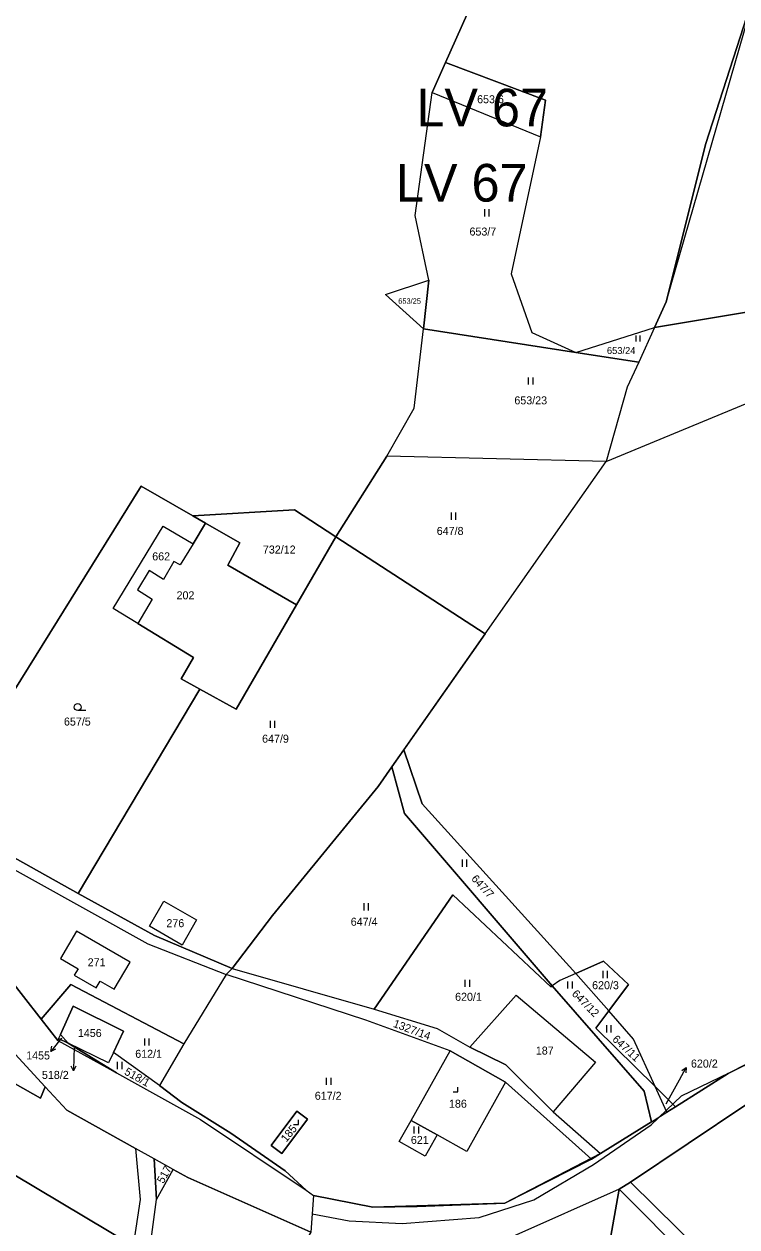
# Model space of a CAD drawing. Extents: x -588699 to -585793, y -1060280 to -1056731.
# Drawn here: x -586434.8 to -586283.2, y -1058797.6 to -1058542.2 of the extents above; entities that cross this region are included whole.
import ezdxf

# ---------------------------------------------------------------- set-up
doc = ezdxf.new("R2010")
doc.units = 0
for name, color, linetype in [('Druh pozemku', 7, 'Continuous'), ('Lesy', 7, 'Continuous'), ('Parcela nároku', 7, 'Continuous'), ('Parcelní číslo', 7, 'Continuous'), ('Silnice', 7, 'Continuous'), ('Vnější obvod_převzatý', 7, 'Continuous')]:
    doc.layers.add(name, color=color, linetype=linetype)

msp = doc.modelspace()

# ---------------------------------------------------------------- linework, layer by layer
at = {"layer": 'Druh pozemku'}
for p, q in [((-586336.91, -1058581.52), (-586336.91, -1058583.02)), ((-586335.89, -1058583.02), (-586335.89, -1058581.52)), ((-586304.73, -1058608.32), (-586304.73, -1058609.63)), ((-586303.84, -1058609.63), (-586303.84, -1058608.32)), ((-586327.62, -1058617.24), (-586327.62, -1058618.74)), ((-586326.59, -1058618.74), (-586326.59, -1058617.24)), ((-586344.02, -1058645.94), (-586344.02, -1058647.44)), ((-586342.99, -1058647.44), (-586342.99, -1058645.94)), ((-586421.6, -1058687.98), (-586423.35, -1058687.98)), ((-586382.45, -1058690.15), (-586382.45, -1058691.65)), ((-586381.43, -1058691.65), (-586381.43, -1058690.15)), ((-586341.66, -1058719.63), (-586341.66, -1058721.13)), ((-586340.64, -1058721.13), (-586340.64, -1058719.63)), ((-586362.55, -1058728.9), (-586362.55, -1058730.4)), ((-586361.53, -1058730.4), (-586361.53, -1058728.9)), ((-586311.78, -1058743.27), (-586311.78, -1058744.77)), ((-586310.76, -1058744.77), (-586310.76, -1058743.27)), ((-586341.06, -1058745.17), (-586341.06, -1058746.67)), ((-586340.04, -1058746.67), (-586340.04, -1058745.17)), ((-586319.26, -1058745.51), (-586319.26, -1058747.01)), ((-586318.23, -1058747.01), (-586318.23, -1058745.51)), ((-586310.98, -1058754.81), (-586310.98, -1058756.31)), ((-586309.95, -1058756.31), (-586309.95, -1058754.81)), ((-586409.18, -1058757.63), (-586409.18, -1058759.13)), ((-586408.16, -1058759.13), (-586408.16, -1058757.63)), ((-586414.96, -1058762.6), (-586414.96, -1058764.1)), ((-586413.94, -1058764.1), (-586413.94, -1058762.6)), ((-586370.52, -1058765.96), (-586370.52, -1058767.46)), ((-586369.49, -1058767.46), (-586369.49, -1058765.96)), ((-586351.9, -1058776.3), (-586351.9, -1058777.8)), ((-586350.88, -1058777.8), (-586350.88, -1058776.3))]:
    msp.add_line(p, q, dxfattribs=at)
for points in [[(-586343.59, -1058768.97), (-586342.59, -1058768.97), (-586342.59, -1058767.97)], [(-586377.46, -1058775.91), (-586376.46, -1058775.91), (-586376.46, -1058774.91)]]:
    msp.add_lwpolyline(points, dxfattribs=at)
msp.add_circle((-586423.35, -1058687.23), 0.75, dxfattribs=at)
at = {"layer": 'Lesy'}
for p, q in [((-586453.29, -1058710.03), (-586409.84, -1058640.32)), ((-586409.84, -1058640.32), (-586398.87, -1058646.62)), ((-586398.87, -1058646.62), (-586377.28, -1058645.37)), ((-586377.28, -1058645.37), (-586368.48, -1058651.09)), ((-586368.48, -1058651.09), (-586336.76, -1058671.67)), ((-586336.76, -1058671.67), (-586356.59, -1058699.92)), ((-586356.59, -1058699.92), (-586353.93, -1058709.84)), ((-586353.93, -1058709.84), (-586322.51, -1058746.43)), ((-586322.51, -1058746.43), (-586302.94, -1058768.81)), ((-586302.94, -1058768.81), (-586301.44, -1058775.29)), ((-586301.44, -1058775.29), (-586312.24, -1058782.04)), ((-586312.24, -1058782.04), (-586332.61, -1058792.6)), ((-586373.25, -1058790.93), (-586373.84, -1058798.77)), ((-586360.65, -1058793.45), (-586373.25, -1058790.93)), ((-586332.61, -1058792.6), (-586360.65, -1058793.45))]:
    msp.add_line(p, q, dxfattribs=at)
at = {"layer": 'Parcela nároku'}
for points in [[(-586268.05, -1058328.41), (-586289.8, -1058351.3), (-586283.9, -1058355.94), (-586342.08, -1058362.25), (-586342.17, -1058367.06), (-586359.81, -1058378.3), (-586352.74, -1058390.79), (-586353.7, -1058435.93), (-586332.59, -1058441.57), (-586335.85, -1058529.42), (-586345.17, -1058550.32), (-586323.92, -1058558.36), (-586325.03, -1058566.12), (-586331.21, -1058595.25), (-586326.84, -1058607.7), (-586317.47, -1058611.91), (-586300.78, -1058606.62), (-586298.3, -1058601.18), (-586289.88, -1058567.53), (-586265.74, -1058492.92)], [(-586421.78, -1058450.97), (-586453.56, -1058551.24), (-586502.57, -1058620.88), (-586520.5, -1058656.37), (-586480.5, -1058691.28), (-586476.88, -1058694.44), (-586465.74, -1058686.35), (-586466.89, -1058702.91), (-586453.29, -1058710.03), (-586409.84, -1058640.32), (-586398.87, -1058646.62), (-586377.28, -1058645.37), (-586368.48, -1058651.09), (-586357.64, -1058633.94), (-586351.82, -1058623.75), (-586349.88, -1058606.93), (-586357.96, -1058599.65), (-586348.75, -1058596.58), (-586351.64, -1058582.85), (-586348.03, -1058556.69), (-586345.17, -1058550.32), (-586335.85, -1058529.42)], [(-586265.74, -1058492.92), (-586289.88, -1058567.53), (-586298.3, -1058601.18), (-586300.78, -1058606.62), (-586247.3, -1058597.74)], [(-586373.84, -1058798.77), (-586399.97, -1058787.16), (-586403.04, -1058785.45), (-586407.1, -1058783.18), (-586411.04, -1058780.99), (-586425.65, -1058772.84), (-586430.27, -1058767.88), (-586439.92, -1058757.51), (-586447.03, -1058749.88), (-586459.59, -1058740.72), (-586472.09, -1058731.41), (-586506.38, -1058706.88), (-586526.71, -1058690.04), (-586530.42, -1058687.01), (-586542.32, -1058678.44), (-586548.16, -1058673.91), (-586559.3, -1058665.26), (-586580.93, -1058648.48), (-586604.33, -1058636.33), (-586618.94, -1058628.76), (-586660.99, -1058605.82)], [(-586261.43, -1058753.04), (-586285.09, -1058765.06), (-586296.34, -1058772.1), (-586300.65, -1058767.84), (-586305.23, -1058757.79), (-586310.51, -1058751.75), (-586306.33, -1058746.16), (-586311.6, -1058741.16), (-586317.47, -1058743.79), (-586350.13, -1058707.76), (-586354.04, -1058696.29), (-586336.76, -1058671.67), (-586311.06, -1058635.05), (-586279.02, -1058621.82)], [(-586438.6, -1058743.85), (-586431.1, -1058753.5), (-586427.58, -1058758.03), (-586415.11, -1058764.91), (-586397.23, -1058774.79), (-586374.81, -1058789.86), (-586373.25, -1058790.93), (-586360.65, -1058793.45), (-586351.24, -1058793.26), (-586332.61, -1058792.6), (-586314.18, -1058783.25), (-586312.24, -1058782.04), (-586301.44, -1058775.29), (-586298.18, -1058773.25), (-586296.34, -1058772.1), (-586285.09, -1058765.06), (-586261.43, -1058753.04)], [(-586281.39, -1058771.68), (-586305.84, -1058788.1), (-586308.29, -1058789.63), (-586330.85, -1058799.68)]]:
    msp.add_lwpolyline(points, dxfattribs=at)
for points in [[(-586323.92, -1058558.36), (-586345.17, -1058550.32), (-586348.03, -1058556.69), (-586325.03, -1058566.12)], [(-586351.64, -1058582.85), (-586348.03, -1058556.69), (-586325.03, -1058566.12), (-586331.21, -1058595.25), (-586326.84, -1058607.7), (-586317.47, -1058611.91), (-586349.88, -1058606.93), (-586348.75, -1058596.58)], [(-586357.96, -1058599.65), (-586348.75, -1058596.58), (-586349.88, -1058606.93)], [(-586306.55, -1058619.31), (-586311.06, -1058635.05), (-586279.02, -1058621.82), (-586249.14, -1058613.3), (-586234.81, -1058604.08), (-586247.3, -1058597.74), (-586300.78, -1058606.62), (-586304.12, -1058613.96)], [(-586351.82, -1058623.75), (-586349.88, -1058606.93), (-586317.47, -1058611.91), (-586304.12, -1058613.96), (-586306.55, -1058619.31), (-586311.06, -1058635.05), (-586357.64, -1058633.94)], [(-586317.47, -1058611.91), (-586300.78, -1058606.62), (-586304.12, -1058613.96)], [(-586357.64, -1058633.94), (-586368.48, -1058651.09), (-586336.76, -1058671.67), (-586311.06, -1058635.05)], [(-586410.57, -1058669.52), (-586415.81, -1058666.33), (-586405.17, -1058648.81), (-586398.83, -1058652.55), (-586396.17, -1058648.17), (-586398.87, -1058646.62), (-586409.84, -1058640.32), (-586453.29, -1058710.03), (-586423.23, -1058726.84), (-586397.39, -1058683.42), (-586401.38, -1058681.22), (-586398.73, -1058676.74)], [(-586377.28, -1058645.37), (-586398.87, -1058646.62), (-586396.17, -1058648.17), (-586388.93, -1058652.34), (-586391.45, -1058657.09), (-586376.83, -1058665.52), (-586368.48, -1058651.09)], [(-586405.17, -1058648.81), (-586398.83, -1058652.55), (-586401.57, -1058657.05), (-586402.91, -1058656.29), (-586405.15, -1058660.13), (-586408.15, -1058658.25), (-586410.64, -1058662.37), (-586407.5, -1058664.31), (-586410.57, -1058669.52), (-586415.81, -1058666.33)], [(-586408.15, -1058658.25), (-586410.64, -1058662.37), (-586407.5, -1058664.31), (-586410.57, -1058669.52), (-586398.73, -1058676.74), (-586401.38, -1058681.22), (-586397.39, -1058683.42), (-586389.66, -1058687.68), (-586376.83, -1058665.52), (-586391.45, -1058657.09), (-586388.93, -1058652.34), (-586396.17, -1058648.17), (-586398.83, -1058652.55), (-586401.57, -1058657.05), (-586402.91, -1058656.29), (-586405.15, -1058660.13)], [(-586376.83, -1058665.52), (-586389.66, -1058687.68), (-586397.39, -1058683.42), (-586423.23, -1058726.84), (-586407.04, -1058735.71), (-586390.54, -1058742.72), (-586381.99, -1058731.47), (-586359.52, -1058704.1), (-586356.59, -1058699.92), (-586354.04, -1058696.29), (-586336.76, -1058671.67), (-586368.48, -1058651.09)], [(-586466.89, -1058702.91), (-586476.88, -1058694.44), (-586480.5, -1058691.28), (-586482.21, -1058692.9), (-586478.78, -1058695.92), (-586470.92, -1058702.85), (-586408.45, -1058737.5), (-586391.83, -1058744.03), (-586390.54, -1058742.72), (-586407.04, -1058735.71), (-586423.23, -1058726.84), (-586453.29, -1058710.03)], [(-586470.92, -1058702.85), (-586408.45, -1058737.5), (-586391.83, -1058744.03), (-586400.77, -1058758.77), (-586424.85, -1058746.15), (-586431.1, -1058753.5), (-586438.6, -1058743.85), (-586445.6, -1058736.95), (-586488.15, -1058707.45), (-586478.78, -1058695.92)], [(-586356.59, -1058699.92), (-586354.04, -1058696.29), (-586350.13, -1058707.76), (-586317.47, -1058743.79), (-586320.87, -1058745.31), (-586322.51, -1058746.43), (-586353.93, -1058709.84)], [(-586356.59, -1058699.92), (-586359.52, -1058704.1), (-586381.99, -1058731.47), (-586390.54, -1058742.72), (-586360.33, -1058751.36), (-586343.6, -1058727.08), (-586322.83, -1058746.65), (-586322.51, -1058746.43), (-586353.93, -1058709.84)], [(-586398.12, -1058732.45), (-586401.19, -1058737.79), (-586408.13, -1058733.75), (-586405.07, -1058728.44)], [(-586408.13, -1058733.75), (-586405.07, -1058728.44), (-586398.12, -1058732.45), (-586401.19, -1058737.79)], [(-586302.94, -1058768.81), (-586322.51, -1058746.43), (-586322.83, -1058746.65), (-586343.6, -1058727.08), (-586360.33, -1058751.36), (-586346.95, -1058755.46), (-586340, -1058759.44), (-586330.2, -1058748.45), (-586313.29, -1058762.64), (-586322.31, -1058773.19), (-586312.24, -1058782.04), (-586301.44, -1058775.29)], [(-586305.84, -1058788.1), (-586281.39, -1058771.68), (-586256.73, -1058759.17), (-586215.7, -1058740.44), (-586185.96, -1058731.13), (-586193.49, -1058744.57), (-586219.2, -1058783.33), (-586231.36, -1058799.16), (-586261.7, -1058840.18), (-586266.42, -1058830.14), (-586283.38, -1058808.16), (-586290.74, -1058803.04)], [(-586427.04, -1058740.65), (-586423.26, -1058742.82), (-586424.12, -1058744.2), (-586419.42, -1058746.85), (-586418.62, -1058745.46), (-586415.58, -1058747.17), (-586412.18, -1058741.42), (-586423.62, -1058734.82)], [(-586423.26, -1058742.82), (-586424.12, -1058744.2), (-586419.42, -1058746.85), (-586418.62, -1058745.46), (-586415.58, -1058747.17), (-586412.18, -1058741.42), (-586423.62, -1058734.82), (-586427.04, -1058740.65)], [(-586494.27, -1058770.47), (-586491.99, -1058772.91), (-586481.47, -1058783.92), (-586476.12, -1058778.86), (-586480.09, -1058774.77), (-586478.86, -1058773.56), (-586481.88, -1058770.42), (-586483.12, -1058771.65), (-586486.65, -1058768.06), (-586473.21, -1058764.89), (-586411.55, -1058801.66), (-586414.16, -1058809.35), (-586490.14, -1058782.82), (-586546.76, -1058750.88), (-586536, -1058737.73), (-586500.07, -1058758.34), (-586503, -1058761.17)], [(-586311.6, -1058741.16), (-586306.33, -1058746.16), (-586310.51, -1058751.75), (-586317.47, -1058743.79)], [(-586340, -1058759.44), (-586332.4, -1058763.21), (-586322.31, -1058773.19), (-586312.24, -1058782.04), (-586314.18, -1058783.25), (-586332.41, -1058766.86), (-586344.22, -1058760.25), (-586362.11, -1058753.72), (-586391.83, -1058744.03), (-586390.54, -1058742.72), (-586360.33, -1058751.36), (-586346.95, -1058755.46)], [(-586310.51, -1058751.75), (-586317.47, -1058743.79), (-586320.87, -1058745.31), (-586322.51, -1058746.43), (-586302.94, -1058768.81), (-586301.44, -1058775.29), (-586298.18, -1058773.25), (-586300.65, -1058767.84), (-586313.25, -1058755.41)], [(-586431.1, -1058753.5), (-586424.85, -1058746.15), (-586400.77, -1058758.77), (-586406.01, -1058767.63), (-586415.78, -1058760.56), (-586413.64, -1058756.06), (-586424.35, -1058750.78), (-586427.03, -1058756.78), (-586427.41, -1058757.64), (-586427.58, -1058758.03)], [(-586346.98, -1058778.11), (-586349.49, -1058782.59), (-586355.02, -1058779.49), (-586352.51, -1058775.02), (-586344.22, -1058760.25), (-586362.11, -1058753.72), (-586391.83, -1058744.03), (-586400.77, -1058758.77), (-586406.01, -1058767.63), (-586401.23, -1058771.24), (-586390.81, -1058777.7), (-586379.27, -1058785.7), (-586374.81, -1058789.86), (-586373.25, -1058790.93), (-586360.65, -1058793.45), (-586351.24, -1058793.26), (-586332.61, -1058792.6), (-586314.18, -1058783.25), (-586332.41, -1058766.86), (-586340.68, -1058781.64)], [(-586340, -1058759.44), (-586330.2, -1058748.45), (-586313.29, -1058762.64), (-586322.31, -1058773.19), (-586332.4, -1058763.21)], [(-586448.02, -1058760.9), (-586431.3, -1058770.3), (-586430.27, -1058767.88), (-586425.65, -1058772.84), (-586411.04, -1058780.99), (-586410.09, -1058791.78), (-586411.55, -1058801.66), (-586473.21, -1058764.89), (-586458.53, -1058750.26), (-586462.12, -1058759.77), (-586449.39, -1058764.8)], [(-586424.35, -1058750.78), (-586413.64, -1058756.06), (-586415.78, -1058760.56), (-586416.83, -1058762.76), (-586425.38, -1058758.62), (-586427.03, -1058756.78)], [(-586305.23, -1058757.79), (-586310.51, -1058751.75), (-586313.25, -1058755.41), (-586300.65, -1058767.84)], [(-586448.02, -1058760.9), (-586446.03, -1058755.27), (-586439.92, -1058757.51), (-586430.27, -1058767.88), (-586431.3, -1058770.3)], [(-586425.38, -1058758.62), (-586427.41, -1058757.64), (-586427.58, -1058758.03), (-586415.11, -1058764.91)], [(-586427.03, -1058756.78), (-586427.41, -1058757.64), (-586425.38, -1058758.62)], [(-586379.27, -1058785.7), (-586390.81, -1058777.7), (-586401.23, -1058771.24), (-586406.01, -1058767.63), (-586415.78, -1058760.56), (-586416.83, -1058762.76), (-586425.38, -1058758.62), (-586415.11, -1058764.91), (-586397.23, -1058774.79), (-586374.81, -1058789.86)], [(-586352.51, -1058775.02), (-586344.22, -1058760.25), (-586332.41, -1058766.86), (-586340.68, -1058781.64), (-586346.98, -1058778.11)], [(-586300.65, -1058767.84), (-586296.34, -1058772.1), (-586298.18, -1058773.25)], [(-586376.81, -1058773.08), (-586374.54, -1058774.76), (-586379.99, -1058782.04), (-586382.26, -1058780.34)], [(-586382.26, -1058780.34), (-586379.99, -1058782.04), (-586374.54, -1058774.76), (-586376.81, -1058773.08)], [(-586355.02, -1058779.49), (-586352.51, -1058775.02), (-586346.98, -1058778.11), (-586349.49, -1058782.59)], [(-586414.92, -1058811.53), (-586416.96, -1058817.42), (-586414.02, -1058818.61), (-586411.03, -1058810.24), (-586407.58, -1058799.23), (-586406.6, -1058791.8), (-586407.1, -1058783.18), (-586411.04, -1058780.99), (-586410.09, -1058791.78), (-586411.55, -1058801.66), (-586414.16, -1058809.35)], [(-586403.04, -1058785.45), (-586407.1, -1058783.18), (-586406.6, -1058791.8)], [(-586411.03, -1058810.24), (-586407.58, -1058799.23), (-586406.6, -1058791.8), (-586403.04, -1058785.45), (-586399.97, -1058787.16), (-586373.84, -1058798.77), (-586387.33, -1058821.26)], [(-586308.29, -1058789.63), (-586330.85, -1058799.68), (-586338.52, -1058801.23), (-586355.15, -1058802.25), (-586358.44, -1058801.82), (-586326.2, -1058823.63), (-586315.44, -1058829.9)], [(-586270.72, -1058830.12), (-586284.05, -1058811.77), (-586293.09, -1058804.81), (-586308.29, -1058789.63), (-586315.44, -1058829.9), (-586305.28, -1058835.83), (-586288.31, -1058851.23), (-586277.39, -1058861.56), (-586265.16, -1058839.87)], [(-586308.29, -1058789.63), (-586305.84, -1058788.1), (-586290.74, -1058803.04), (-586283.38, -1058808.16), (-586266.42, -1058830.14), (-586261.7, -1058840.18), (-586232.96, -1058858.44), (-586210.37, -1058875.49), (-586200.6, -1058882.87), (-586192.2, -1058897.74), (-586179.85, -1058912.85), (-586154.34, -1058936.8), (-586157.46, -1058938.24), (-586175.66, -1058921.09), (-586195.55, -1058899.89), (-586202.53, -1058884.11), (-586233.05, -1058861.42), (-586263.54, -1058842.71), (-586265.16, -1058839.87), (-586270.72, -1058830.12), (-586284.05, -1058811.77), (-586293.09, -1058804.81)]]:
    msp.add_lwpolyline(points, close=True, dxfattribs=at)
at = {"layer": 'Parcelní číslo'}
for p, q in [((-586427.2, -1058758.04), (-586429.09, -1058760.37)), ((-586426.83, -1058757.58), (-586427.2, -1058758.04)), ((-586424.19, -1058761.5), (-586424.26, -1058764.5)), ((-586424.14, -1058759.67), (-586424.19, -1058761.5)), ((-586295.49, -1058766.41), (-586294.02, -1058763.79)), ((-586298.32, -1058771.47), (-586295.49, -1058766.41))]:
    msp.add_line(p, q, dxfattribs=at)
for points in [[(-586428.07, -1058759.91), (-586429.09, -1058760.37), (-586428.85, -1058759.28)], [(-586423.74, -1058763.51), (-586424.26, -1058764.5), (-586424.74, -1058763.49)], [(-586294.95, -1058764.42), (-586294.02, -1058763.79), (-586294.08, -1058764.91)]]:
    msp.add_lwpolyline(points, dxfattribs=at)
at = {"layer": 'Silnice'}
msp.add_lwpolyline([(-586373.54, -1058794.85), (-586365.65, -1058796.34), (-586354.41, -1058796.91), (-586338.05, -1058795.61), (-586326.41, -1058791.86), (-586313.73, -1058784.41), (-586301.45, -1058775.93), (-586295.01, -1058769.76), (-586268.58, -1058757.07), (-586233.66, -1058742.25), (-586214.67, -1058734.19), (-586188.01, -1058726.64), (-586154.96, -1058722.22), (-586103.5, -1058715.34), (-586059.32, -1058711.74), (-586003.34, -1058710.18), (-585938.7, -1058711.89), (-585887.87, -1058713.23), (-585856.14, -1058714.07), (-585836.32, -1058716.3), (-585816.87, -1058720.94)], dxfattribs=at)
at = {"layer": 'Vnější obvod_převzatý'}
msp.add_lwpolyline([(-586300.78, -1058606.62), (-586298.3, -1058601.18), (-586277.81, -1058530.23), (-586265.74, -1058492.92), (-586259.54, -1058475.58), (-586239.3, -1058427.6), (-586218.3, -1058371.81)], dxfattribs=at)

# ---------------------------------------------------------------- texts
at = {"layer": 'Parcela nároku'}
for s, height, p in [('653/6', 1.7, (-586338.47, -1058559)), ('653/7', 1.7, (-586340.09, -1058587.1)), ('653/25', 1.14, (-586355.23, -1058601.58)), ('653/24', 1.48, (-586310.88, -1058612.26)), ('653/23', 1.7, (-586330.55, -1058622.95)), ('647/8', 1.7, (-586347.05, -1058650.68)), ('662', 1.7, (-586407.52, -1058656.08)), ('732/12', 1.7, (-586384, -1058654.63)), ('202', 1.7, (-586402.35, -1058664.35)), ('657/5', 1.7, (-586426.28, -1058691.16)), ('647/9', 1.7, (-586384.17, -1058694.8)), ('276', 1.7, (-586404.51, -1058733.98)), ('647/4', 1.7, (-586365.33, -1058733.67)), ('271', 1.7, (-586421.24, -1058742.28)), ('620/3', 1.7, (-586314.03, -1058747.15)), ('620/1', 1.7, (-586343.15, -1058749.61)), ('1456', 1.7, (-586423.32, -1058757.3)), ('1455', 0.1, (-586426.95, -1058757.58)), ('518/2', 0.1, (-586424.31, -1058759.67)), ('612/1', 1.7, (-586411.13, -1058761.72)), ('187', 1.7, (-586325.99, -1058761.03)), ('617/2', 1.7, (-586372.97, -1058770.63)), ('186', 1.7, (-586344.45, -1058772.32)), ('620/2', 0.1, (-586298.51, -1058771.47)), ('621', 1.7, (-586352.55, -1058780.01))]:
    msp.add_text(s, height=height, dxfattribs=at).set_placement(p)
for s, rotation, p in [('647/7', 312.64, (-586339.83, -1058723.79)), ('647/12', 314.7549, (-586318.46, -1058748.27)), ('1327/14', 339.6468, (-586356.46, -1058755.12)), ('647/11', 317.37, (-586309.87, -1058757.97)), ('518/1', 330.8369, (-586413.6, -1058765.16)), ('185', 50.6687, (-586379.03, -1058779.77)), ('517', 60.9503, (-586405.16, -1058788.55))]:
    msp.add_text(s, height=1.7, rotation=rotation, dxfattribs=at).set_placement(p)
at = {"layer": 'Parcelní číslo'}
for s, p in [('1455', (-586434.31, -1058762.07)), ('620/2', (-586293.02, -1058763.79)), ('518/2', (-586430.96, -1058766.2))]:
    msp.add_text(s, height=1.7, dxfattribs=at).set_placement(p)
at = {"layer": 'Vnější obvod_převzatý'}
for p in [(-586351.37, -1058563.92), (-586355.71, -1058579.89)]:
    msp.add_text('LV 67', height=8, dxfattribs=at).set_placement(p)

doc.saveas('drawing.dxf')
